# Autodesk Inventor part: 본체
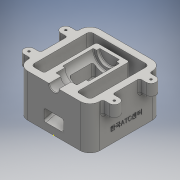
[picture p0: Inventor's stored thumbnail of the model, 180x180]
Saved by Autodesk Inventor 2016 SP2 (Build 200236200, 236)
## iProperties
Created: 2018-01
Part Number: 본체
Material: Generic
Document SubType Name: Modeling
Designer: Administrator
Density: 1 g/cm^3
Appearance: Default
Author: Administrator
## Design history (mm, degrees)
sketch "스케치1"
  geometry: L1 (55, -55)-(-55, -55); L2 (-55, -55)-(-55, 55); L3 (-55, 55)-(55, 55); L4 (55, 55)-(55, -55); L5 (55, -55)-(-55, 55); L6 (-55, -55)-(55, 55); 1 further point
  constraints: 12 end point, 2 midpoint, 2 parallel, 1 horizontal, 1 perpendicular
  dimensions: "d0" = 110 distance between parallel lines of L1 L3; "d1" = 110 distance between parallel lines of L4 L2
extrude "돌출1" new body sketch "스케치1" distance "d2" = 65; taper "d3" = 0 deg
sketch "스케치2"
  geometry: L1 (-55, -55)-(55, -55) reference; L2 (-55, 55)-(-55, -55) reference; L3 (55, -55)-(55, 55) reference; L4 (-65, -35.5)-(-55, -35.5); L5 (-65, -20.5)-(-55, -20.5); L6 (-65, 20.5)-(-55, 20.5); L7 (-65, 35.5)-(-55, 35.5); L8 (55, -35.5)-(65, -35.5); L9 (55, -20.5)-(65, -20.5); L10 (55, 20.5)-(65, 20.5); L11 (55, 35.5)-(65, 35.5); A1 r 7.5 centre (-65, -28) between (-65, -20.5) and (-65, -35.5); A2 r 7.5 centre (-65, 28) between (-65, 35.5) and (-65, 20.5); A3 r 7.5 centre (65, -28) between (65, -35.5) and (65, -20.5); A4 r 7.5 centre (65, 28) between (65, 20.5) and (65, 35.5); 1 further point
  constraints: 16 end point, 8 horizontal, 8 point on circle, 8 point on line, 8 tangent, 4 centre point, 2 horizontal alignment, 2 vertical alignment
  dimensions: "d4" = 15 diameter of A1; "d5" = 15 diameter of A2; "d6" = 27 distance from line of A1.centre L1; "d7" = 56 distance of A2.centre A1.centre; "d8" = 10 distance from line of L2 A1.centre; "d9" = 15 diameter of A3; "d10" = 15 diameter of A4; "d11" = 10 distance from line of A3.centre L3
extrude "돌출2" join sketch "스케치2" distance "d12" = 20; taper "d13" = 0 deg
sketch "스케치3"
  geometry: L1 (-55, -55)-(55, -55) reference; L2 (55, -55)-(55, -35.5) reference; L3 (55, -35.5)-(65, -35.5) reference; L4 (65, -20.5)-(55, -20.5) reference; L5 (55, -20.5)-(55, 20.5) reference; L6 (55, 20.5)-(65, 20.5) reference; L7 (65, 35.5)-(55, 35.5) reference; L8 (55, 35.5)-(55, 55) reference; L9 (55, 55)-(-55, 55) reference; L10 (-55, 55)-(-55, 35.5) reference; L11 (-55, 35.5)-(-65, 35.5) reference; L12 (-65, 20.5)-(-55, 20.5) reference; L13 (-55, 20.5)-(-55, -20.5) reference; L14 (-55, -20.5)-(-65, -20.5) reference; L15 (-65, -35.5)-(-55, -35.5) reference; L16 (-55, -35.5)-(-55, -55) reference; A1 r 7.5 centre (-65, 28) between (-65, 35.5) and (-65, 20.5) reference; A2 r 7.5 centre (65, 28) between (65, 20.5) and (65, 35.5) reference; A3 r 7.5 centre (65, -28) between (65, -35.5) and (65, -20.5) reference; A4 r 7.5 centre (65, -28) between (65, -35.5) and (65, -20.5) reference; A5 r 7.5 centre (65, 28) between (65, 20.5) and (65, 35.5) reference; A6 r 7.5 centre (-65, 28) between (-65, 35.5) and (-65, 20.5) reference; A7 r 7.5 centre (-65, -28) between (-65, -20.5) and (-65, -35.5) reference; A8 r 7.5 centre (-65, -28) between (-65, -20.5) and (-65, -35.5) reference; 5 further points
  constraints: 4 coincident
hole "구멍1" sketch "스케치3" at (-65, 28), (-65, -28), (65, 28), (65, -28) diameter "d14" = 3.242; stored, may be unused: countersink angle "d18" = 90 deg, drill point angle "d20" = 118 deg; dims "d15" = 9, "d16" = 4, "d17" = 2, "d19" = 11
sketch "스케치4"
  geometry: L1 (-55, 20.5)-(-55, -20.5) reference; L2 (55, -20.5)-(55, 20.5) reference; L3 (55, 55)-(-55, 55) reference; L4 (-25, -55.439)-(-25, 35); L5 (-25, 35)-(25, 35); L6 (25, 35)-(25, -55); L7 (-55, -55)-(55, -55) reference; L8 (-25, -45)-(-45, -45); L9 (-45, -45)-(-45, 45); L10 (-45, 45)-(45, 45); L11 (45, 45)-(45, -45); L12 (45, -45)-(25, -45); 1 further point
  constraints: 16 end point, 5 point on line, 4 perpendicular, 1 horizontal, 1 parallel, 1 vertical
  dimensions: "d26" = 30 distance between parallel lines of L4 L1; "d27" = 30 distance between parallel lines of L2 L6; "d28" = 20 distance between parallel lines of L3 L5; "d29" = 10 distance between parallel lines of L7 L8; "d30" = 10 distance between parallel lines of L1 L9; "d31" = 10 distance between parallel lines of L10 L3; "d32" = 10 distance between parallel lines of L2 L11
extrude "돌출3" cut sketch "스케치4" distance "d33" = 65; taper "d34" = 0 deg
sketch "스케치7"
  geometry: 1 further point
sketch "스케치8"
  geometry: L1 (-35.5, 65)-(-55, 65) reference; L2 (55, 65)-(35.5, 65) reference; L3 (-55, 65)-(55, 65); L4 (-55, 65)-(-55, 72.5); L5 (-55, 72.5)-(-36, 72.5); L6 (-36, 72.5)-(-36, 81); L7 (-36, 81)-(-22, 81); L8 (-22, 81)-(-22, 85); L9 (-22, 85)-(25, 85); L10 (25, 85)-(25, 80); L11 (25, 80)-(30, 80); L12 (30, 80)-(30, 65); L13 (-45, 65)-(45, 65) reference; 1 further point
  constraints: 20 end point, 7 perpendicular, 2 vertical, 1 horizontal, 1 point on line
  dimensions: "d37" = 15 diameter of L5 L3; "d38" = 19 distance between parallel lines of L6 L4; "d39" = 32 diameter of L7 L3; "d40" = 14 distance between parallel lines of L8 L6; "d41" = 40 diameter of L9 L3; "d42" = 47 distance between parallel lines of L10 L8; "d43" = 30 diameter of L11 L3; "d44" = 5 distance between parallel lines of L12 L10
revolve "회전1" sketch "스케치8" stored, may be unused: angle "d45" = 90 deg
sketch "스케치10"
  geometry: L1 (-17, 39.243)-(-55, 29.061); L2 (-22, 65)-(25, 65) reference; L3 (-55, 0)-(-55, 65) reference; L4 (20, 31.157)-(-55, 11.061); L5 (35, 65)-(35, 0) reference; L6 (35, 30)-(-35.681, 11.061); L7 (-45, 0)-(35, 0) reference; L8 (-17, 53)-(-17, 39.243); L9 (20, 53)-(20, 31.157); L10 (20, 53)-(-17, 53); L11 (-35.681, 11.061)-(-35.681, 0); L12 (25, 65)-(25, 50) reference; L13 (-22, 65)-(-22, 49) reference; 1 further point
  constraints: 14 end point, 4 point on line, 2 parallel, 2 vertical, 1 horizontal, 1 horizontal alignment, 1 perpendicular
  dimensions: "d53" = 75 deg angle of L1 L3; "d54" = 30 distance from line of L7 L6.start; "d55" = 5 distance between parallel lines of L6 L4; "d56" = 18 distance of L4.end L1.end; "d57" = 37 distance between parallel lines of L9 L8; "d58" = 12 distance between parallel lines of L10 L2; "d90" = 5 distance between parallel lines of L12 L9; "d91" = 5 distance between parallel lines of L8 L13 (derived)
extrude "돌출5" cut sketch "스케치10" stored distance "d59" = 30; taper "d60" = 0 deg
sketch "스케치11"
  geometry: L1 (0, 110)-(0, 0) reference; L2 (0, 0)-(-65, 0) reference; 3 further points
  constraints: 1 coincident, 1 other
  dimensions: "d62" = 20 distance from line of L1 point (-20, 55); "d63" = 55 distance from line of point (-20, 55) L2
feature "엠보싱1" sketch "스케치11" dims "d0" = 110, "d1" = 110, "d4" = 15, "d5" = 15, "d6" = 27, "d7" = 56, "d8" = 10, "d9" = 15, "d10" = 15, "d11" = 10, "d64" = 0.5, "d65" = 0
sketch "스케치14"
  geometry: L1 (20, 31.157)-(-55, 11.061) reference; L2 (35, 65)-(35, 0) reference; L3 (35, 30)-(-45, 8.564); L4 (35, 30)-(35, 0); L5 (-55, 0)-(55, 0) reference; L6 (-45, 8.564)-(-45, 0); L7 (-55, 0)-(-55, 65) reference; 1 further point
  constraints: 6 end point, 2 point on line, 1 collinear, 1 parallel, 1 perpendicular
  dimensions: "d75" = 10 distance between parallel lines of L6 L7; "d76" = 5 distance between parallel lines of L3 L1
extrude "돌출7" cut sketch "스케치14" stored distance "d73" = 50; taper "d74" = 0 deg
fillet "모깎기1" dims "d77" = 5
fillet "모깎기3" dims "d79" = 1
fillet "모깎기4" dims "d80" = 3
fillet "모깎기5" dims "d81" = 3
fillet "모깎기7" dims "d83" = 3
fillet "모깎기9" dims "d85" = 15
fillet "모깎기13" dims "d89" = 3
fillet "모깎기14" dims "d95" = 3
fillet "모깎기15" dims "d96" = 3
fillet "모깎기16" dims "d97" = 3
node "솔리드1"
node "투영된 루프1"
other parameters: "d51" = 37
